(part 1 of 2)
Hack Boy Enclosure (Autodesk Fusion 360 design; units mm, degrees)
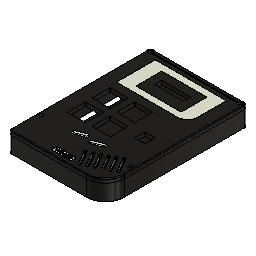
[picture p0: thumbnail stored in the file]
part number: 2026-02-14-20-05-58-561
sketch "Sketch1" plane through (0, 0, 0) normal (0, 0, 1) x axis (1, 0, 0)
  line L1 (63.94, 0) -> (0, 0)
  line L2 (63.94, 79.2) -> (63.94, 0)
  line L3 (0, 79.2) -> (63.94, 79.2)
  line L4 (0, 0) -> (0, 79.2)
  point P1 (0, 0)
  point P2 (0, 0)
  point P5 (0, 79.2)
  horizontal L1
  vertical L2
  horizontal L3
  vertical L4
  coincident P1 P2
  dimension "d1" distance P2 P5 = 79.2
  dimension "d2" distance L2 L4 = 63.94
sketch "Sketch3" plane through (0, 0, 0) normal (0, 0, 1) x axis (1, 0, 0)
  line L1 (0, 0) -> (0, 79.2)
  line L2 (63.94, 79.2) -> (63.94, 0)
  line L3 (0, 79.2) -> (63.94, 79.2)
  line L4 (63.94, 0) -> (0, 0)
  line L5 (69.47, 84.73) -> (-5.53, 84.73)
  line L6 (69.47, -25.27) -> (69.47, 84.73)
  line L7 (-5.53, -25.27) -> (69.47, -25.27)
  line L8 (-5.53, 84.73) -> (-5.53, -25.27)
  circle C1 centre (66.47, -3) radius 1.45
  circle C2 centre (-2.53, -3) radius 1.45
  circle C3 centre (-2.53, 81.73) radius 1.45
  circle C4 centre (66.47, 81.73) radius 1.45
  point P7 (-2.53, -3)
  point P6 (66.47, -3)
  point P9 (66.47, 81.73)
  point P8 (-2.53, 81.73)
  horizontal L5
  vertical L6
  horizontal L7
  vertical L8
  dimension "d11" diameter C1 = 2.9
  dimension "d14" diameter C2 = 2.9
  dimension "d20" diameter C3 = 2.9
  dimension "d23" diameter C4 = 2.9
  dimension "d30" distance L1 L8 = 5.53
  dimension "d31" distance L2 L6 = 5.53
  dimension "d32" distance L3 L5 = 5.53
  dimension "d33" distance L4 L7 = 25.27
  dimension "d35" distance P7 L8 = 3
  dimension "d36" distance L4 P7 = 3
  dimension "d37" distance L4 P6 = 3
  dimension "d38" distance P6 L6 = 3
  dimension "d39" distance P9 L6 = 3
  dimension "d40" distance P9 L5 = 3
  dimension "d41" distance P8 L5 = 3
  dimension "d42" distance P8 L8 = 3
extrude "Extrude1" new body sketch "Sketch3" along normal blind 3
extrude "Extrude2" add of existing geometry blind 10
extrude "Extrude3" add sketch "Sketch1" along normal blind 3
fillet "Fillet1" radius 15
fillet "Fillet2" radius 2
fillet "Fillet3" radius 2
fillet "Fillet4" radius 2
sketch "Sketch4" plane through (0, 0, 0) normal (0, 0, 1) x axis (1, 0, 0)
extrude "Extrude4" new body of existing geometry blind 3
move "Move1"
surface_patch "SurfacePatch5"
extrude "Extrude9" add of existing geometry blind -7
move "Move3"
sketch "Sketch10" plane through (0, 0, 3) normal (0, 0, 1) x axis (1, 0, 0)
move "Move4"
sketch "plate-2026-02-15T00_46_07.612Z" plane through (0, 0, 16) normal (0, 0, 1) x axis (1, 0, 0)
  line L1 (19.1671, 42.1434) -> (6.1671, 42.1434)
  line L2 (19.1671, 28.1434) -> (6.1671, 28.1434)
  line L3 (5.6671, 28.6434) -> (5.6671, 41.6434)
  line L4 (19.6671, 28.6434) -> (19.6671, 41.6434)
  line L5 (38.2171, 42.1434) -> (25.2171, 42.1434)
  line L6 (38.2171, 28.1434) -> (25.2171, 28.1434)
  line L7 (24.7171, 28.6434) -> (24.7171, 41.6434)
  line L8 (38.7171, 28.6434) -> (38.7171, 41.6434)
  line L9 (19.1671, 23.0934) -> (6.1671, 23.0934)
  line L10 (19.1671, 9.0934) -> (6.1671, 9.0934)
  line L11 (5.6671, 9.5934) -> (5.6671, 22.5934)
  line L12 (19.6671, 9.5934) -> (19.6671, 22.5934)
  line L13 (38.2171, 23.0934) -> (25.2171, 23.0934)
  line L14 (38.2171, 9.0934) -> (25.2171, 9.0934)
  line L15 (24.7171, 9.5934) -> (24.7171, 22.5934)
  line L16 (38.7171, 9.5934) -> (38.7171, 22.5934)
  line L17 (41.2421, 6.5684) -> (3.1421, 6.5684)
  line L18 (41.2421, 44.6684) -> (3.1421, 44.6684)
  line L19 (3.1421, 44.6684) -> (3.1421, 6.5684)
  line L20 (41.2421, 44.6684) -> (41.2421, 6.5684)
  arc A1 centre (6.1671, 41.6434) radius 0.5 clockwise from (5.6671, 41.6434) to (6.1671, 42.1434)
  arc A2 centre (19.1671, 41.6434) radius 0.5 clockwise from (19.1671, 42.1434) to (19.6671, 41.6434)
  arc A3 centre (6.1671, 28.6434) radius 0.5 clockwise from (6.1671, 28.1434) to (5.6671, 28.6434)
  arc A4 centre (19.1671, 28.6434) radius 0.5 clockwise from (19.6671, 28.6434) to (19.1671, 28.1434)
  arc A5 centre (25.2171, 41.6434) radius 0.5 clockwise from (24.7171, 41.6434) to (25.2171, 42.1434)
  arc A6 centre (38.2171, 41.6434) radius 0.5 clockwise from (38.2171, 42.1434) to (38.7171, 41.6434)
  arc A7 centre (25.2171, 28.6434) radius 0.5 clockwise from (25.2171, 28.1434) to (24.7171, 28.6434)
  arc A8 centre (38.2171, 28.6434) radius 0.5 clockwise from (38.7171, 28.6434) to (38.2171, 28.1434)
  arc A9 centre (6.1671, 22.5934) radius 0.5 clockwise from (5.6671, 22.5934) to (6.1671, 23.0934)
  arc A10 centre (19.1671, 22.5934) radius 0.5 clockwise from (19.1671, 23.0934) to (19.6671, 22.5934)
  arc A11 centre (6.1671, 9.5934) radius 0.5 clockwise from (6.1671, 9.0934) to (5.6671, 9.5934)
  arc A12 centre (19.1671, 9.5934) radius 0.5 clockwise from (19.6671, 9.5934) to (19.1671, 9.0934)
  arc A13 centre (25.2171, 22.5934) radius 0.5 clockwise from (24.7171, 22.5934) to (25.2171, 23.0934)
  arc A14 centre (38.2171, 22.5934) radius 0.5 clockwise from (38.2171, 23.0934) to (38.7171, 22.5934)
  arc A15 centre (25.2171, 9.5934) radius 0.5 clockwise from (25.2171, 9.0934) to (24.7171, 9.5934)
  arc A16 centre (38.2171, 9.5934) radius 0.5 clockwise from (38.7171, 9.5934) to (38.2171, 9.0934)
extrude "Extrude10" cut sketch "plate-2026-02-15T00_46_07.612Z" profile of L1 L2 L3 L4 A1 A2 A3 A4 L5 L6 L7 L8 A5 A6 A7 A8 L9 L10 L11 L12 A9 A10 A11 A12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 against normal blind 4
sketch "plate-2026-03-27T04_05_42.671Z" plane through (0, 0, 16) normal (0, 0, 1) x axis (1, 0, 0)
  line L1 (59.3897, 28.9519) -> (46.3897, 28.9519)
  line L2 (59.3897, 14.9519) -> (46.3897, 14.9519)
  line L3 (45.8897, 15.4519) -> (45.8897, 28.4519)
  line L4 (59.8897, 15.4519) -> (59.8897, 28.4519)
  line L5 (62.4147, 12.4269) -> (43.3647, 12.4269)
  line L6 (62.4147, 31.4769) -> (43.3647, 31.4769)
  line L7 (43.3647, 31.4769) -> (43.3647, 12.4269)
  line L8 (62.4147, 31.4769) -> (62.4147, 12.4269)
  arc A1 centre (46.3897, 28.4519) radius 0.5 clockwise from (45.8897, 28.4519) to (46.3897, 28.9519)
  arc A2 centre (59.3897, 28.4519) radius 0.5 clockwise from (59.3897, 28.9519) to (59.8897, 28.4519)
  arc A3 centre (46.3897, 15.4519) radius 0.5 clockwise from (46.3897, 14.9519) to (45.8897, 15.4519)
  arc A4 centre (59.3897, 15.4519) radius 0.5 clockwise from (59.8897, 15.4519) to (59.3897, 14.9519)
extrude "Extrude11" cut sketch "plate-2026-03-27T04_05_42.671Z" profile of L1 L2 L3 L4 A1 A2 A3 A4 against normal blind 4
sketch "Sketch13" plane through (0, 0, 16) normal (0, 0, 1) x axis (-1, 0, 0)
  line L1 (-45.8897, -28.4519) -> (-45.8897, -15.4519)
  line L2 (-59.3897, -28.9519) -> (-46.3897, -28.9519)
  line L3 (-59.8897, -15.4519) -> (-59.8897, -28.4519)
  line L4 (-46.3897, -14.9519) -> (-59.3897, -14.9519)
  line L5 (-5.6671, -41.6434) -> (-5.6671, -28.6434)
  line L6 (-19.1671, -42.1434) -> (-6.1671, -42.1434)
  line L7 (-19.6671, -28.6434) -> (-19.6671, -41.6434)
  line L8 (-6.1671, -28.1434) -> (-19.1671, -28.1434)
  line L9 (-5.6671, -22.5934) -> (-5.6671, -9.5934)
  line L10 (-19.1671, -23.0934) -> (-6.1671, -23.0934)
  line L11 (-19.6671, -9.5934) -> (-19.6671, -22.5934)
  line L12 (-6.1671, -9.0934) -> (-19.1671, -9.0934)
  line L13 (-24.7171, -41.6434) -> (-24.7171, -28.6434)
  line L14 (-38.2171, -42.1434) -> (-25.2171, -42.1434)
  line L15 (-38.7171, -28.6434) -> (-38.7171, -41.6434)
  line L16 (-25.2171, -28.1434) -> (-38.2171, -28.1434)
  line L17 (-24.7171, -22.5934) -> (-24.7171, -9.5934)
  line L18 (-38.2171, -23.0934) -> (-25.2171, -23.0934)
  line L19 (-38.7171, -9.5934) -> (-38.7171, -22.5934)
  line L20 (-25.2171, -9.0934) -> (-38.2171, -9.0934)
  line L21 (3.53, -84.73) -> (-67.47, -84.73)
  line L22 (5.53, 23.27) -> (5.53, -82.73)
  line L23 (-54.47, 25.27) -> (3.53, 25.27)
  line L24 (-69.47, -82.73) -> (-69.47, 10.27)
  line L25 (-43.16, -67.23) -> (-20.78, -67.23)
  line L26 (-43.16, -61.65) -> (-43.16, -67.23)
  line L27 (-20.78, -61.65) -> (-43.16, -61.65)
  line L28 (-20.78, -67.23) -> (-20.78, -61.65)
  arc A1 centre (-46.3897, -28.4519) radius 0.5 clockwise from (-45.8897, -28.4519) to (-46.3897, -28.9519)
  arc A2 centre (-59.3897, -28.4519) radius 0.5 clockwise from (-59.3897, -28.9519) to (-59.8897, -28.4519)
  arc A3 centre (-59.3897, -15.4519) radius 0.5 clockwise from (-59.8897, -15.4519) to (-59.3897, -14.9519)
  arc A4 centre (-46.3897, -15.4519) radius 0.5 clockwise from (-46.3897, -14.9519) to (-45.8897, -15.4519)
  arc A5 centre (-6.1671, -41.6434) radius 0.5 clockwise from (-5.6671, -41.6434) to (-6.1671, -42.1434)
  arc A6 centre (-19.1671, -41.6434) radius 0.5 clockwise from (-19.1671, -42.1434) to (-19.6671, -41.6434)
  arc A7 centre (-19.1671, -28.6434) radius 0.5 clockwise from (-19.6671, -28.6434) to (-19.1671, -28.1434)
  arc A8 centre (-6.1671, -28.6434) radius 0.5 clockwise from (-6.1671, -28.1434) to (-5.6671, -28.6434)
  arc A9 centre (-6.1671, -22.5934) radius 0.5 clockwise from (-5.6671, -22.5934) to (-6.1671, -23.0934)
  arc A10 centre (-19.1671, -22.5934) radius 0.5 clockwise from (-19.1671, -23.0934) to (-19.6671, -22.5934)
  arc A11 centre (-19.1671, -9.5934) radius 0.5 clockwise from (-19.6671, -9.5934) to (-19.1671, -9.0934)
  arc A12 centre (-6.1671, -9.5934) radius 0.5 clockwise from (-6.1671, -9.0934) to (-5.6671, -9.5934)
  arc A13 centre (-25.2171, -41.6434) radius 0.5 clockwise from (-24.7171, -41.6434) to (-25.2171, -42.1434)
  arc A14 centre (-38.2171, -41.6434) radius 0.5 clockwise from (-38.2171, -42.1434) to (-38.7171, -41.6434)
  arc A15 centre (-38.2171, -28.6434) radius 0.5 clockwise from (-38.7171, -28.6434) to (-38.2171, -28.1434)
  arc A16 centre (-25.2171, -28.6434) radius 0.5 clockwise from (-25.2171, -28.1434) to (-24.7171, -28.6434)
  arc A17 centre (-25.2171, -22.5934) radius 0.5 clockwise from (-24.7171, -22.5934) to (-25.2171, -23.0934)
  arc A18 centre (-38.2171, -22.5934) radius 0.5 clockwise from (-38.2171, -23.0934) to (-38.7171, -22.5934)
  arc A19 centre (-38.2171, -9.5934) radius 0.5 clockwise from (-38.7171, -9.5934) to (-38.2171, -9.0934)
  arc A20 centre (-25.2171, -9.5934) radius 0.5 clockwise from (-25.2171, -9.0934) to (-24.7171, -9.5934)
  arc A21 centre (-67.47, -82.73) radius 2 clockwise from (-67.47, -84.73) to (-69.47, -82.73)
  arc A22 centre (3.53, -82.73) radius 2 clockwise from (5.53, -82.73) to (3.53, -84.73)
  arc A23 centre (3.53, 23.27) radius 2 clockwise from (3.53, 25.27) to (5.53, 23.27)
  arc A24 centre (-54.47, 10.27) radius 15 clockwise from (-69.47, 10.27) to (-54.47, 25.27)
  circle C1 centre (-66.47, -81.73) radius 1.45
  circle C2 centre (-66.47, 3) radius 1.45
  circle C3 centre (2.53, 3) radius 1.45
  circle C4 centre (2.53, -81.73) radius 1.45
  point P78 (-20.78, -67.23)
  point P81 (-20.78, -61.65)
  point P79 (-43.16, -67.23)
  horizontal L25
  vertical L26
  horizontal L27
  vertical L28
  dimension "d73" distance P78 P81 = 5.58
  dimension "d74" distance P78 P79 = 22.38
  dimension "d75" distance L22 L28 = 26.31
  dimension "d76" distance L21 L25 = 17.5
extrude "Extrude12" cut sketch "Sketch13" profile of L25 L26 L27 L28 against normal blind 4
sketch "Sketch14" plane through (0, 0, 16) normal (0, 0, 1) x axis (-1, 0, 0)
  line L1 (-43.16, -61.65) -> (-43.16, -67.23)
  line L2 (-20.78, -61.65) -> (-43.16, -61.65)
  line L3 (-20.78, -67.23) -> (-20.78, -61.65)
  line L4 (-43.16, -67.23) -> (-20.78, -67.23)
  line L5 (-45.8897, -28.4519) -> (-45.8897, -15.4519)
  line L6 (-59.3897, -28.9519) -> (-46.3897, -28.9519)
  line L7 (-59.8897, -15.4519) -> (-59.8897, -28.4519)
  line L8 (-46.3897, -14.9519) -> (-59.3897, -14.9519)
  line L9 (-5.6671, -41.6434) -> (-5.6671, -28.6434)
  line L10 (-19.1671, -42.1434) -> (-6.1671, -42.1434)
  line L11 (-19.6671, -28.6434) -> (-19.6671, -41.6434)
  line L12 (-6.1671, -28.1434) -> (-19.1671, -28.1434)
  line L13 (-5.6671, -22.5934) -> (-5.6671, -9.5934)
  line L14 (-19.1671, -23.0934) -> (-6.1671, -23.0934)
  line L15 (-19.6671, -9.5934) -> (-19.6671, -22.5934)
  line L16 (-6.1671, -9.0934) -> (-19.1671, -9.0934)
  line L17 (-24.7171, -41.6434) -> (-24.7171, -28.6434)
  line L18 (-38.2171, -42.1434) -> (-25.2171, -42.1434)
  line L19 (-38.7171, -28.6434) -> (-38.7171, -41.6434)
  line L20 (-25.2171, -28.1434) -> (-38.2171, -28.1434)
  line L21 (-24.7171, -22.5934) -> (-24.7171, -9.5934)
  line L22 (-38.2171, -23.0934) -> (-25.2171, -23.0934)
  line L23 (-38.7171, -9.5934) -> (-38.7171, -22.5934)
  line L24 (-25.2171, -9.0934) -> (-38.2171, -9.0934)
  line L25 (3.53, -84.73) -> (-67.47, -84.73)
  line L26 (5.53, 23.27) -> (5.53, -82.73)
  line L27 (-54.47, 25.27) -> (3.53, 25.27)
  line L28 (-69.47, -82.73) -> (-69.47, 10.27)
  line L29 (-58.47, -78.4365) -> (-5.47, -78.4365)
  line L30 (-59.47, -56.4365) -> (-59.47, -77.4365)
  line L31 (-5.47, -48.4365) -> (-51.47, -48.4365)
  line L32 (-4.47, -77.4365) -> (-4.47, -49.4365)
  arc A1 centre (-46.3897, -28.4519) radius 0.5 clockwise from (-45.8897, -28.4519) to (-46.3897, -28.9519)
  arc A2 centre (-59.3897, -28.4519) radius 0.5 clockwise from (-59.3897, -28.9519) to (-59.8897, -28.4519)
  arc A3 centre (-59.3897, -15.4519) radius 0.5 clockwise from (-59.8897, -15.4519) to (-59.3897, -14.9519)
  arc A4 centre (-46.3897, -15.4519) radius 0.5 clockwise from (-46.3897, -14.9519) to (-45.8897, -15.4519)
  arc A5 centre (-6.1671, -41.6434) radius 0.5 clockwise from (-5.6671, -41.6434) to (-6.1671, -42.1434)
  arc A6 centre (-19.1671, -41.6434) radius 0.5 clockwise from (-19.1671, -42.1434) to (-19.6671, -41.6434)
  arc A7 centre (-19.1671, -28.6434) radius 0.5 clockwise from (-19.6671, -28.6434) to (-19.1671, -28.1434)
  arc A8 centre (-6.1671, -28.6434) radius 0.5 clockwise from (-6.1671, -28.1434) to (-5.6671, -28.6434)
  arc A9 centre (-6.1671, -22.5934) radius 0.5 clockwise from (-5.6671, -22.5934) to (-6.1671, -23.0934)
  arc A10 centre (-19.1671, -22.5934) radius 0.5 clockwise from (-19.1671, -23.0934) to (-19.6671, -22.5934)
  arc A11 centre (-19.1671, -9.5934) radius 0.5 clockwise from (-19.6671, -9.5934) to (-19.1671, -9.0934)
  arc A12 centre (-6.1671, -9.5934) radius 0.5 clockwise from (-6.1671, -9.0934) to (-5.6671, -9.5934)
  arc A13 centre (-25.2171, -41.6434) radius 0.5 clockwise from (-24.7171, -41.6434) to (-25.2171, -42.1434)
  arc A14 centre (-38.2171, -41.6434) radius 0.5 clockwise from (-38.2171, -42.1434) to (-38.7171, -41.6434)
  arc A15 centre (-38.2171, -28.6434) radius 0.5 clockwise from (-38.7171, -28.6434) to (-38.2171, -28.1434)
  arc A16 centre (-25.2171, -28.6434) radius 0.5 clockwise from (-25.2171, -28.1434) to (-24.7171, -28.6434)
  arc A17 centre (-25.2171, -22.5934) radius 0.5 clockwise from (-24.7171, -22.5934) to (-25.2171, -23.0934)
  arc A18 centre (-38.2171, -22.5934) radius 0.5 clockwise from (-38.2171, -23.0934) to (-38.7171, -22.5934)
  arc A19 centre (-38.2171, -9.5934) radius 0.5 clockwise from (-38.7171, -9.5934) to (-38.2171, -9.0934)
  arc A20 centre (-25.2171, -9.5934) radius 0.5 clockwise from (-25.2171, -9.0934) to (-24.7171, -9.5934)
  arc A21 centre (-67.47, -82.73) radius 2 clockwise from (-67.47, -84.73) to (-69.47, -82.73)
  arc A22 centre (3.53, -82.73) radius 2 clockwise from (5.53, -82.73) to (3.53, -84.73)
  arc A23 centre (3.53, 23.27) radius 2 clockwise from (3.53, 25.27) to (5.53, 23.27)
  arc A24 centre (-54.47, 10.27) radius 15 clockwise from (-69.47, 10.27) to (-54.47, 25.27)
  circle C1 centre (-66.47, -81.73) radius 1.45
  circle C2 centre (-66.47, 3) radius 1.45
  circle C3 centre (2.53, 3) radius 1.45
  circle C4 centre (2.53, -81.73) radius 1.45
  arc A25 centre (-51.47, -56.4365) radius 8 clockwise from (-59.47, -56.4365) to (-51.47, -48.4365)
  arc A26 centre (-58.47, -77.4365) radius 1 clockwise from (-58.47, -78.4365) to (-59.47, -77.4365)
  arc A27 centre (-5.47, -77.4365) radius 1 clockwise from (-4.47, -77.4365) to (-5.47, -78.4365)
  arc A28 centre (-5.47, -49.4365) radius 1 clockwise from (-5.47, -48.4365) to (-4.47, -49.4365)
  horizontal L29
  vertical L30
  horizontal L31
  vertical L32
  tangent L30 A25
  tangent L31 A25
  tangent L29 A26
  tangent L30 A26
  tangent L29 A27
  tangent L32 A27
  equal A26 A27
  tangent L31 A28
  tangent L32 A28
  dimension "d81" distance L26 L32 = 10
  dimension "d82" distance L25 L29 = 6.2935
  dimension "d83" radius A25 = 8
  dimension "d84" radius A26 = 1
  dimension "d85" radius A28 = 1
sketch "Sketch15" plane through (0, 0, 16) normal (0, 0, 1) x axis (-1, 0, 0)
  line L1 (-49.47, -73.4365) -> (-14.47, -73.4365)
  line L2 (-49.47, -53.4365) -> (-49.47, -73.4365)
  line L3 (-14.47, -53.4365) -> (-49.47, -53.4365)
  line L4 (-14.47, -73.4365) -> (-14.47, -53.4365)
  line L5 (-59.47, -56.4365) -> (-59.47, -77.4365)
  line L6 (-58.47, -78.4365) -> (-5.47, -78.4365)
  point P2 (-14.47, -73.4365)
  point P3 (-49.47, -73.4365)
  point P5 (-14.47, -53.4365)
  horizontal L1
  vertical L2
  horizontal L3
  vertical L4
  dimension "d86" distance P2 P3 = 35
  dimension "d87" distance P2 P5 = 20
  dimension "d88" distance L2 L5 = 10
  dimension "d89" distance L1 L6 = 5
extrude "Extrude13" cut sketch "Sketch14" profile of L1 L2 L3 L4 L29 L30 L31 L32 A25 A26 A27 A28 against normal blind 0.1
extrude "Extrude14" cut sketch "Sketch15" profile of L1 L2 L3 L4 against normal blind 0.2
sketch "Sketch16" plane through (0, 0, 16) normal (0, 0, 1) x axis (-1, 0, 0)
  line L1 (-4.47, -77.4365) -> (-4.47, -49.4365)
  line L2 (-58.47, -78.4365) -> (-5.47, -78.4365)
  line L3 (-59.47, -56.4365) -> (-59.47, -77.4365)
  line L4 (-5.47, -48.4365) -> (-51.47, -48.4365)
  line L5 (-45.8897, -28.4519) -> (-45.8897, -15.4519)
  line L6 (-59.3897, -28.9519) -> (-46.3897, -28.9519)
  line L7 (-59.8897, -15.4519) -> (-59.8897, -28.4519)
  line L8 (-46.3897, -14.9519) -> (-59.3897, -14.9519)
  line L9 (-5.6671, -41.6434) -> (-5.6671, -28.6434)
  line L10 (-19.1671, -42.1434) -> (-6.1671, -42.1434)
  line L11 (-19.6671, -28.6434) -> (-19.6671, -41.6434)
  line L12 (-6.1671, -28.1434) -> (-19.1671, -28.1434)
  line L13 (-5.6671, -22.5934) -> (-5.6671, -9.5934)
  line L14 (-19.1671, -23.0934) -> (-6.1671, -23.0934)
  line L15 (-19.6671, -9.5934) -> (-19.6671, -22.5934)
  line L16 (-6.1671, -9.0934) -> (-19.1671, -9.0934)
  line L17 (-24.7171, -41.6434) -> (-24.7171, -28.6434)
  line L18 (-38.2171, -42.1434) -> (-25.2171, -42.1434)
  line L19 (-38.7171, -28.6434) -> (-38.7171, -41.6434)
  line L20 (-25.2171, -28.1434) -> (-38.2171, -28.1434)
  line L21 (-24.7171, -22.5934) -> (-24.7171, -9.5934)
  line L22 (-38.2171, -23.0934) -> (-25.2171, -23.0934)
  line L23 (-38.7171, -9.5934) -> (-38.7171, -22.5934)
  line L24 (-25.2171, -9.0934) -> (-38.2171, -9.0934)
  line L25 (3.53, -84.73) -> (-67.47, -84.73)
  line L26 (5.53, 23.27) -> (5.53, -82.73)
  line L27 (-54.47, 25.27) -> (3.53, 25.27)
  line L28 (-69.47, -82.73) -> (-69.47, 10.27)
  line L29 (-65.0763, -82.13) -> (1.1363, -82.13)
  line L30 (-65.0763, -81.33) -> (1.1363, -81.33)
  line L31 (5.53, -82.13) -> (3.9237, -82.13)
  line L32 (5.53, -81.33) -> (3.9237, -81.33)
  line L33 (-69.47, -82.13) -> (-67.8637, -82.13)
  line L34 (-69.47, -81.33) -> (-67.8637, -81.33)
  line L35 (2.13, -84.73) -> (2.13, -83.1237)
  line L36 (2.93, -84.73) -> (2.93, -83.1237)
  line L37 (-66.87, -84.73) -> (-66.87, -83.1237)
  line L38 (-66.07, -84.73) -> (-66.07, -83.1237)
  line L39 (4.18, -81.33) -> (4.18, -82.13)
  line L40 (2.13, -83.38) -> (2.93, -83.38)
  line L41 (0.88, -81.33) -> (0.88, -82.13)
  line L42 (-64.82, -81.33) -> (-64.82, -82.13)
  line L43 (-66.87, -83.38) -> (-66.07, -83.38)
  line L44 (-68.12, -81.33) -> (-68.12, -82.13)
  arc A1 centre (-5.47, -77.4365) radius 1 clockwise from (-4.47, -77.4365) to (-5.47, -78.4365)
  arc A2 centre (-58.47, -77.4365) radius 1 clockwise from (-58.47, -78.4365) to (-59.47, -77.4365)
  arc A3 centre (-51.47, -56.4365) radius 8 clockwise from (-59.47, -56.4365) to (-51.47, -48.4365)
  arc A4 centre (-5.47, -49.4365) radius 1 clockwise from (-5.47, -48.4365) to (-4.47, -49.4365)
  arc A5 centre (-46.3897, -28.4519) radius 0.5 clockwise from (-45.8897, -28.4519) to (-46.3897, -28.9519)
  arc A6 centre (-59.3897, -28.4519) radius 0.5 clockwise from (-59.3897, -28.9519) to (-59.8897, -28.4519)
  arc A7 centre (-59.3897, -15.4519) radius 0.5 clockwise from (-59.8897, -15.4519) to (-59.3897, -14.9519)
  arc A8 centre (-46.3897, -15.4519) radius 0.5 clockwise from (-46.3897, -14.9519) to (-45.8897, -15.4519)
  arc A9 centre (-6.1671, -41.6434) radius 0.5 clockwise from (-5.6671, -41.6434) to (-6.1671, -42.1434)
  arc A10 centre (-19.1671, -41.6434) radius 0.5 clockwise from (-19.1671, -42.1434) to (-19.6671, -41.6434)
  arc A11 centre (-19.1671, -28.6434) radius 0.5 clockwise from (-19.6671, -28.6434) to (-19.1671, -28.1434)
  arc A12 centre (-6.1671, -28.6434) radius 0.5 clockwise from (-6.1671, -28.1434) to (-5.6671, -28.6434)
  arc A13 centre (-6.1671, -22.5934) radius 0.5 clockwise from (-5.6671, -22.5934) to (-6.1671, -23.0934)
  arc A14 centre (-19.1671, -22.5934) radius 0.5 clockwise from (-19.1671, -23.0934) to (-19.6671, -22.5934)
  arc A15 centre (-19.1671, -9.5934) radius 0.5 clockwise from (-19.6671, -9.5934) to (-19.1671, -9.0934)
  arc A16 centre (-6.1671, -9.5934) radius 0.5 clockwise from (-6.1671, -9.0934) to (-5.6671, -9.5934)
  arc A17 centre (-25.2171, -41.6434) radius 0.5 clockwise from (-24.7171, -41.6434) to (-25.2171, -42.1434)
  arc A18 centre (-38.2171, -41.6434) radius 0.5 clockwise from (-38.2171, -42.1434) to (-38.7171, -41.6434)
  arc A19 centre (-38.2171, -28.6434) radius 0.5 clockwise from (-38.7171, -28.6434) to (-38.2171, -28.1434)
  arc A20 centre (-25.2171, -28.6434) radius 0.5 clockwise from (-25.2171, -28.1434) to (-24.7171, -28.6434)
  arc A21 centre (-25.2171, -22.5934) radius 0.5 clockwise from (-24.7171, -22.5934) to (-25.2171, -23.0934)
  arc A22 centre (-38.2171, -22.5934) radius 0.5 clockwise from (-38.2171, -23.0934) to (-38.7171, -22.5934)
  arc A23 centre (-38.2171, -9.5934) radius 0.5 clockwise from (-38.7171, -9.5934) to (-38.2171, -9.0934)
  arc A24 centre (-25.2171, -9.5934) radius 0.5 clockwise from (-25.2171, -9.0934) to (-24.7171, -9.5934)
  arc A25 centre (-67.47, -82.73) radius 2 clockwise from (-67.47, -84.73) to (-69.47, -82.73)
  arc A26 centre (3.53, -82.73) radius 2 clockwise from (5.53, -82.73) to (3.53, -84.73)
  arc A27 centre (3.53, 23.27) radius 2 clockwise from (3.53, 25.27) to (5.53, 23.27)
  arc A28 centre (-54.47, 10.27) radius 15 clockwise from (-69.47, 10.27) to (-54.47, 25.27)
  circle C1 centre (-66.47, -81.73) radius 1.45
  circle C2 centre (-66.47, 3) radius 1.45
  circle C3 centre (2.53, 3) radius 1.45
  circle C4 centre (2.53, -81.73) radius 1.45
  point P90 (1.1363, -82.13)
  point P91 (-65.0763, -82.13)
  point P92 (1.1363, -81.33)
  point P93 (-65.0763, -81.33)
  point P94 (3.9237, -82.13)
  point P95 (5.53, -82.13)
  point P96 (3.9237, -81.33)
  point P97 (5.53, -81.33)
  point P98 (-67.8637, -82.13)
  point P99 (-69.47, -82.13)
  point P100 (-67.8637, -81.33)
  point P101 (-69.47, -81.33)
  point P102 (2.13, -83.1237)
  point P103 (2.13, -84.73)
  point P104 (2.93, -83.1237)
  point P105 (2.93, -84.73)
  point P106 (-66.87, -83.1237)
  point P107 (-66.87, -84.73)
  point P108 (-66.07, -83.1237)
  point P109 (-66.07, -84.73)
  point P110 (4.18, -82.13)
  point P111 (4.18, -81.33)
  point P112 (2.93, -83.38)
  point P113 (2.13, -83.38)
  point P114 (0.88, -82.13)
  point P115 (0.88, -81.33)
  point P116 (-64.82, -82.13)
  point P117 (-64.82, -81.33)
  point P118 (-66.07, -83.38)
  point P119 (-66.87, -83.38)
  point P120 (-68.12, -82.13)
  point P121 (-68.12, -81.33)
  point P89 (2.53, -81.73)
  point P86 (-66.47, -81.73)
  coincident C4 P90
  coincident C1 P91
  parallel L25 L29
  coincident C4 P92
  coincident C1 P93
  parallel L25 L30
  coincident C4 P94
  coincident L26 P95
  perpendicular L26 L31
  coincident C4 P96
  coincident L26 P97
  perpendicular L26 L32
  coincident C1 P98
  coincident L28 P99
  perpendicular L28 L33
  coincident C1 P100
  coincident L28 P101
  perpendicular L28 L34
  coincident C4 P102
  coincident L25 P103
  perpendicular L25 L35
  coincident C4 P104
  coincident L25 P105
  perpendicular L25 L36
  coincident C1 P106
  coincident L25 P107
  perpendicular L25 L37
  coincident C1 P108
  coincident L25 P109
  perpendicular L25 L38
  coincident L31 P110
  coincident L32 P111
  perpendicular L32 L39
  coincident L36 P112
  coincident L35 P113
  perpendicular L35 L40
  coincident L29 P114
  coincident L30 P115
  perpendicular L30 L41
  coincident L29 P116
  coincident L30 P117
  perpendicular L30 L42
  coincident L38 P118
  coincident L37 P119
  perpendicular L37 L43
  coincident L33 P120
  coincident L34 P121
  perpendicular L34 L44
  dimension "d116" distance P89 L39 = 1.65
  dimension "d117" distance P89 L40 = 1.65
  dimension "d118" distance P89 L41 = 1.65
  dimension "d119" distance P86 L42 = 1.65
  dimension "d120" distance P86 L43 = 1.65
  dimension "d121" distance P86 L44 = 1.65
sketch "Sketch19" plane through (69.47, 0, 0) normal (1, 0, 0) x axis (0, 1, 0)
  line L1 (-10.27, 16) -> (82.73, 16)
  line L2 (-10.27, 13) -> (-10.27, 16)
  line L3 (82.73, 13) -> (-10.27, 13)
  line L4 (82.73, 16) -> (82.73, 13)
  line L5 (82.13, 8.5) -> (82.13, 16)
  line L6 (81.33, 8.5) -> (81.33, 16)
  line L7 (82.73, 8.5) -> (82.13, 8.5)
  line L8 (-10, 8.5) -> (81.33, 8.5)
  line L9 (82.73, 7.7) -> (82.73, 8.5)
  line L10 (-10.3, 7.7) -> (82.73, 7.7)
  line L11 (-10.3, 8.5) -> (-10, 8.5)
  line L12 (-10.3, 8.5) -> (-10.3, 7.7)
  point P6 (82.13, 16)
  point P8 (81.33, 16)
  point P7 (82.13, 8.5)
  point P10 (82.73, 8.5)
  point P12 (82.73, 7.7)
  coincident L1 P6
  perpendicular L1 L5
  coincident L1 P8
  perpendicular L1 L6
  perpendicular L5 L7
  perpendicular L6 L8
  perpendicular L7 L9
  perpendicular L9 L10
  parallel L8 L11
  perpendicular L11 L12
  dimension "d114" distance L5 L6 = 0.8
  dimension "d115" distance L4 L5 = 0.6
  dimension "d122" distance P7 P10 = 0.6
  dimension "d123" distance P10 P12 = 0.8
sketch "Sketch20" plane through (0, 79.2, 0) normal (0, -1, 0) x axis (1, 0, 0)
  line L1 (63.94, 3) -> (0, 3)
  line L2 (63.94, 13) -> (63.94, 3)
  line L3 (0, 13) -> (63.94, 13)
  line L4 (0, 3) -> (0, 13)
extrude "Extrude20" cut sketch "Sketch16" profile of L25 L26 L28 L29 L30 L31 L32 L33 L34 L35 L36 L37 L38 L39 L40 L41 L42 L43 L44 against normal blind 0.2
sketch "Sketch22" plane through (0, 0, 16) normal (0, 0, 1) x axis (-1, 0, 0)
  line L1 (-28.7155, -2.375) -> (-21.198, 0.3612)
  line L2 (-30.3393, -0.8376) -> (-29.9973, -1.7773)
  line L3 (-22.2241, 3.1803) -> (-29.7416, 0.4441)
  line L4 (-20.6003, 1.6429) -> (-20.9423, 2.5826)
  line L5 (-33.6003, 1.6429) -> (-33.9423, 2.5826)
  line L6 (-35.2241, 3.1803) -> (-42.742, 0.444)
  line L7 (-41.7162, -2.3752) -> (-34.198, 0.3612)
  line L8 (-43.3398, -0.8375) -> (-42.998, -1.7773)
  line L9 (5.53, 23.27) -> (5.53, -81.33)
  line L10 (-69.47, 10) -> (-69.47, -81.33)
  arc A1 centre (-29.0576, -1.4353) radius 1 clockwise from (-28.7155, -2.375) to (-29.9973, -1.7773)
  arc A2 centre (-29.3996, -0.4956) radius 1 clockwise from (-30.3393, -0.8376) to (-29.7416, 0.4441)
  arc A3 centre (-21.882, 2.2406) radius 1 clockwise from (-22.2241, 3.1803) to (-20.9423, 2.5826)
  arc A4 centre (-21.54, 1.3009) radius 1 clockwise from (-20.6003, 1.6429) to (-21.198, 0.3612)
  arc A5 centre (-42.4, -0.4957) radius 1 clockwise from (-43.3398, -0.8375) to (-42.742, 0.444)
  arc A6 centre (-34.882, 2.2406) radius 1 clockwise from (-35.2241, 3.1803) to (-33.9423, 2.5826)
  arc A7 centre (-42.0582, -1.4355) radius 1 clockwise from (-41.7162, -2.3752) to (-42.998, -1.7773)
  arc A8 centre (-34.54, 1.3009) radius 1 clockwise from (-33.6003, 1.6429) to (-34.198, 0.3612)
  point P3 (-29.6552, -2.717)
  point P4 (-21.2844, 3.5223)
  point P2 (-20.2583, 0.7032)
  point P31 (-42.6561, -2.7173)
  point P29 (-34.2844, 3.5223)
  point P30 (-33.2583, 0.7032)
  coincident P3 L1
  coincident P3 L2
  tangent L1 A1
  tangent L2 A1
  tangent L2 A2
  tangent L3 A2
  equal A1 A2
  coincident P4 L3
  coincident P4 L4
  tangent L3 A3
  tangent L4 A3
  equal A1 A3
  coincident P2 L1
  coincident P2 L4
  tangent L1 A4
  tangent L4 A4
  equal A1 A4
  coincident P31 L7
  coincident P31 L8
  tangent A7 L7
  tangent A7 L8
  tangent A5 L8
  tangent A5 L6
  equal A5 A7
  coincident P29 L6
  coincident P29 L5
  tangent A6 L6
  tangent A6 L5
  equal A6 A7
  coincident P30 L7
  coincident P30 L5
  tangent A8 L7
  tangent L5 A8
  equal A7 A8
sketch "Sketch23" plane through (0, 0, 16) normal (0, 0, 1) x axis (-1, 0, 0)
  line L1 (-50.0584, 18.8284) -> (-43.5584, 7.5701)
  line L2 (-49.4424, 19.7614) -> (-49.8754, 19.5114)
  line L3 (-42.2594, 8.3201) -> (-48.7594, 19.5784)
  line L4 (-42.8754, 7.3871) -> (-42.4424, 7.6371)
  line L5 (-54.0584, 16.8284) -> (-47.5584, 5.5701)
  line L6 (-46.8754, 5.3871) -> (-46.4424, 5.6371)
  line L7 (-46.2594, 6.3201) -> (-52.7594, 17.5784)
  line L8 (-53.4424, 17.7614) -> (-53.8754, 17.5114)
  line L9 (-50.2594, 4.3201) -> (-56.7594, 15.5784)
  line L10 (-57.4424, 15.7614) -> (-57.8754, 15.5114)
  line L11 (-58.0584, 14.8284) -> (-51.5584, 3.5701)
  line L12 (-50.8754, 3.3871) -> (-50.4424, 3.6371)
  line L13 (-54.2594, 2.3201) -> (-60.7594, 13.5784)
  line L14 (-61.4424, 13.7614) -> (-61.8754, 13.5114)
  line L15 (-62.0584, 12.8284) -> (-55.5584, 1.5701)
  line L16 (-54.8754, 1.3871) -> (-54.4424, 1.6371)
  line L17 (-58.2594, 0.3201) -> (-64.7594, 11.5784)
  line L18 (-65.4424, 11.7614) -> (-65.8754, 11.5114)
  line L19 (-66.0584, 10.8284) -> (-59.5584, -0.4299)
  line L20 (-58.8754, -0.6129) -> (-58.4424, -0.3629)
  line L21 (-38.2594, 10.3201) -> (-44.7594, 21.5784)
  line L22 (-45.4424, 21.7614) -> (-45.8754, 21.5114)
  line L23 (-46.0584, 20.8284) -> (-39.5584, 9.5701)
  line L24 (-38.8754, 9.3871) -> (-38.4424, 9.6371)
  arc A1 centre (-43.1254, 7.8201) radius 0.5 clockwise from (-42.8754, 7.3871) to (-43.5584, 7.5701)
  arc A2 centre (-42.6924, 8.0701) radius 0.5 clockwise from (-42.2594, 8.3201) to (-42.4424, 7.6371)
  arc A3 centre (-49.1924, 19.3284) radius 0.5 clockwise from (-49.4424, 19.7614) to (-48.7594, 19.5784)
  arc A4 centre (-49.6254, 19.0784) radius 0.5 clockwise from (-50.0584, 18.8284) to (-49.8754, 19.5114)
  arc A5 centre (-46.6924, 6.0701) radius 0.5 clockwise from (-46.2594, 6.3201) to (-46.4424, 5.6371)
  arc A6 centre (-47.1254, 5.8201) radius 0.5 clockwise from (-46.8754, 5.3871) to (-47.5584, 5.5701)
  arc A7 centre (-53.6254, 17.0784) radius 0.5 clockwise from (-54.0584, 16.8284) to (-53.8754, 17.5114)
  arc A8 centre (-53.1924, 17.3284) radius 0.5 clockwise from (-53.4424, 17.7614) to (-52.7594, 17.5784)
  arc A9 centre (-57.1924, 15.3284) radius 0.5 clockwise from (-57.4424, 15.7614) to (-56.7594, 15.5784)
  arc A10 centre (-51.1254, 3.8201) radius 0.5 clockwise from (-50.8754, 3.3871) to (-51.5584, 3.5701)
  arc A11 centre (-57.6254, 15.0784) radius 0.5 clockwise from (-58.0584, 14.8284) to (-57.8754, 15.5114)
  arc A12 centre (-50.6924, 4.0701) radius 0.5 clockwise from (-50.2594, 4.3201) to (-50.4424, 3.6371)
  arc A13 centre (-61.1924, 13.3284) radius 0.5 clockwise from (-61.4424, 13.7614) to (-60.7594, 13.5784)
  arc A14 centre (-55.1254, 1.8201) radius 0.5 clockwise from (-54.8754, 1.3871) to (-55.5584, 1.5701)
  arc A15 centre (-61.6254, 13.0784) radius 0.5 clockwise from (-62.0584, 12.8284) to (-61.8754, 13.5114)
  arc A16 centre (-54.6924, 2.0701) radius 0.5 clockwise from (-54.2594, 2.3201) to (-54.4424, 1.6371)
  arc A17 centre (-65.1924, 11.3284) radius 0.5 clockwise from (-65.4424, 11.7614) to (-64.7594, 11.5784)
  arc A18 centre (-59.1254, -0.1799) radius 0.5 clockwise from (-58.8754, -0.6129) to (-59.5584, -0.4299)
  arc A19 centre (-65.6254, 11.0784) radius 0.5 clockwise from (-66.0584, 10.8284) to (-65.8754, 11.5114)
  arc A20 centre (-58.6924, 0.0701) radius 0.5 clockwise from (-58.2594, 0.3201) to (-58.4424, -0.3629)
  arc A21 centre (-45.1924, 21.3284) radius 0.5 clockwise from (-45.4424, 21.7614) to (-44.7594, 21.5784)
  arc A22 centre (-39.1254, 9.8201) radius 0.5 clockwise from (-38.8754, 9.3871) to (-39.5584, 9.5701)
  arc A23 centre (-45.6254, 21.0784) radius 0.5 clockwise from (-46.0584, 20.8284) to (-45.8754, 21.5114)
  arc A24 centre (-38.6924, 10.0701) radius 0.5 clockwise from (-38.2594, 10.3201) to (-38.4424, 9.6371)
  point P2 (-43.3084, 7.1371)
  point P3 (-42.0094, 7.8871)
  point P25 (-47.3084, 5.1371)
  point P18 (-46.0094, 5.8871)
  point P40 (-51.3084, 3.1371)
  point P32 (-50.0094, 3.8871)
  point P54 (-55.3084, 1.1371)
  point P46 (-54.0094, 1.8871)
  point P68 (-59.3084, -0.8629)
  point P60 (-58.0094, -0.1129)
  point P82 (-39.3084, 9.1371)
  point P74 (-38.0094, 9.8871)
  coincident P2 L1
  coincident P2 L4
  tangent L1 A1
  tangent L4 A1
  coincident P3 L3
  coincident P3 L4
  tangent L3 A2
  tangent L4 A2
  equal A1 A2
  tangent L2 A3
  tangent L3 A3
  equal A1 A3
  tangent L1 A4
  tangent L2 A4
  coincident P25 L5
  coincident P25 L6
  tangent L5 A6
  tangent L6 A6
  coincident P18 L7
  coincident P18 L6
  tangent A5 L7
  tangent A5 L6
  equal A5 A6
  tangent A8 L8
  tangent L7 A8
  equal A6 A8
  tangent L5 A7
  tangent A7 L8
  coincident P40 L11
  coincident P40 L12
  tangent A10 L11
  tangent A10 L12
  coincident P32 L9
  coincident P32 L12
  tangent L9 A12
  tangent L12 A12
  equal A10 A12
  tangent A9 L10
  tangent A9 L9
  equal A9 A10
  tangent L11 A11
  tangent L10 A11
  coincident P54 L15
  coincident P54 L16
  tangent A14 L15
  tangent A14 L16
  coincident P46 L13
  coincident P46 L16
  tangent L13 A16
  tangent L16 A16
  equal A14 A16
  tangent A13 L14
  tangent A13 L13
  equal A13 A14
  tangent L15 A15
  tangent L14 A15
  coincident P68 L19
  coincident P68 L20
  tangent A18 L19
  tangent A18 L20
  coincident P60 L17
  coincident P60 L20
  tangent L17 A20
  tangent L20 A20
  equal A18 A20
  tangent A17 L18
  tangent A17 L17
  equal A17 A18
  tangent L19 A19
  tangent L18 A19
  coincident P82 L23
  coincident P82 L24
  tangent A22 L23
  tangent A22 L24
  coincident P74 L21
  coincident P74 L24
  tangent L21 A24
  tangent L24 A24
  equal A22 A24
  tangent A21 L22
  tangent A21 L21
  equal A21 A22
  tangent L23 A23
  tangent L22 A23
  dimension "d145" distance P2 P3 = 1.5
  dimension "d146" radius A1 = 0.5
  dimension "d156" radius A4 = 0.5
  dimension "d175" distance P18 P25 = 1.5
  dimension "d176" radius A6 = 0.5
  dimension "d177" radius A7 = 0.5
  dimension "d178" distance P32 P40 = 1.5
  dimension "d179" radius A10 = 0.5
  dimension "d180" radius A11 = 0.5
  dimension "d181" distance P46 P54 = 1.5
  dimension "d182" radius A14 = 0.5
  dimension "d183" radius A15 = 0.5
  dimension "d184" distance P60 P68 = 1.5
  dimension "d185" radius A18 = 0.5
  dimension "d186" radius A19 = 0.5
  dimension "d187" distance P74 P82 = 1.5
  dimension "d188" radius A22 = 0.5
  dimension "d189" radius A23 = 0.5
extrude "Extrude15" cut sketch "Sketch23" against normal blind 3
extrude "Extrude16" add sketch "Sketch22" profile of L1 L2 L3 L4 A1 A2 A3 A4 A5 A6 A7 L5 A8 L6 L7 L8 along normal blind 0.5
fillet "Fillet5" radius 0.5
fillet "Fillet6" radius 0.5
fillet "Fillet7" radius 0.15
fillet "Fillet8" radius 0.7
fillet "Fillet9" radius 0.7
sketch "Sketch24" plane through (0, 0, 16) normal (0, 0, 1) x axis (-1, 0, 0)
sketch "Sketch25" plane through (0, 0, 16) normal (0, 0, 1) x axis (-1, 0, 0)
  line L1 (-38.47, 22) -> (-25.47, 22)
  line L2 (-39.47, 19) -> (-39.47, 21)
  line L3 (-25.47, 18) -> (-38.47, 18)
  line L4 (-24.47, 21) -> (-24.47, 19)
  line L5 (5.53, 23.27) -> (5.53, -81.33)
  curve K1 (-37.3422, 18.9501) -> (-37.439, 18.8303)
  curve K2 (-37.2294, 19.1163) -> (-37.3422, 18.9501)
  curve K3 (-37.1264, 19.2175) -> (-37.2294, 19.1163)
  curve K4 (-37.0001, 19.2226) -> (-37.1264, 19.2175)
  curve K5 (-36.8722, 19.1852) -> (-37.0001, 19.2226)
  curve K6 (-36.7764, 19.1647) -> (-36.8722, 19.1852)
  curve K7 (-36.4902, 19.1654) -> (-36.7764, 19.1647)
  curve K8 (-36.3848, 19.1705) -> (-36.4902, 19.1654)
  curve K9 (-36.3298, 19.1394) -> (-36.3848, 19.1705)
  curve K10 (-36.1124, 18.8542) -> (-36.3298, 19.1394)
  curve K11 (-36.0763, 18.8096) -> (-36.1124, 18.8542)
  curve K12 (-36.0169, 18.8702) -> (-36.0763, 18.8096)
  curve K13 (-35.8877, 19.0744) -> (-36.0169, 18.8702)
  curve K14 (-35.8587, 19.1153) -> (-35.8877, 19.0744)
  curve K15 (-35.7326, 19.2882) -> (-35.8587, 19.1153)
  curve K16 (-35.6753, 19.3337) -> (-35.7326, 19.2882)
  curve K17 (-35.6001, 19.3437) -> (-35.6753, 19.3337)
  curve K18 (-35.5769, 19.2627) -> (-35.6001, 19.3437)
  curve K19 (-35.6771, 19.0995) -> (-35.5769, 19.2627)
  curve K20 (-35.815, 18.908) -> (-35.6771, 19.0995)
  curve K21 (-35.9339, 18.6824) -> (-35.815, 18.908)
  curve K22 (-35.9612, 18.6022) -> (-35.9339, 18.6824)
  curve K23 (-36.0973, 18.5664) -> (-35.9612, 18.6022)
  curve K24 (-36.1161, 18.5882) -> (-36.0973, 18.5664)
  curve K25 (-36.2433, 18.8099) -> (-36.1161, 18.5882)
  curve K26 (-36.2966, 18.8842) -> (-36.2433, 18.8099)
  curve K27 (-36.3681, 18.9565) -> (-36.2966, 18.8842)
  curve K28 (-36.4589, 18.9942) -> (-36.3681, 18.9565)
  curve K29 (-36.846, 19.016) -> (-36.4589, 18.9942)
  curve K30 (-36.9414, 19.0385) -> (-36.846, 19.016)
  curve K31 (-37.102, 18.986) -> (-36.9414, 19.0385)
  curve K32 (-37.3404, 18.6796) -> (-37.102, 18.986)
  curve K33 (-37.3954, 18.5959) -> (-37.3404, 18.6796)
  curve K34 (-37.5309, 18.5861) -> (-37.3954, 18.5959)
  curve K35 (-37.5748, 18.6731) -> (-37.5309, 18.5861)
  curve K36 (-37.683, 19.0368) -> (-37.5748, 18.6731)
  curve K37 (-37.7398, 19.1887) -> (-37.683, 19.0368)
  curve K38 (-37.7508, 19.2432) -> (-37.7398, 19.1887)
  curve K39 (-37.6718, 19.2952) -> (-37.7508, 19.2432)
  curve K40 (-37.5894, 19.23) -> (-37.6718, 19.2952)
  curve K41 (-37.4954, 18.9357) -> (-37.5894, 19.23)
  curve K42 (-37.4588, 18.8331) -> (-37.4954, 18.9357)
  curve K43 (-37.439, 18.8303) -> (-37.4588, 18.8331)
  curve K44 (-36.8145, 21.2212) -> (-36.9502, 21.2117)
  curve K45 (-36.7768, 21.2193) -> (-36.8145, 21.2212)
  curve K46 (-36.4468, 21.1406) -> (-36.7768, 21.2193)
  curve K47 (-36.2922, 21.1074) -> (-36.4468, 21.1406)
  curve K48 (-36.0061, 20.9949) -> (-36.2922, 21.1074)
  curve K49 (-35.9125, 20.9355) -> (-36.0061, 20.9949)
  curve K50 (-35.7484, 20.7999) -> (-35.9125, 20.9355)
  curve K51 (-35.6992, 20.7298) -> (-35.7484, 20.7999)
  curve K52 (-35.714, 20.639) -> (-35.6992, 20.7298)
  curve K53 (-35.812, 20.6523) -> (-35.714, 20.639)
  curve K54 (-35.8452, 20.6811) -> (-35.812, 20.6523)
  curve K55 (-36.1453, 20.8767) -> (-35.8452, 20.6811)
  curve K56 (-36.4633, 20.9719) -> (-36.1453, 20.8767)
  curve K57 (-36.8966, 21.0382) -> (-36.4633, 20.9719)
  curve K58 (-37.0756, 21.0164) -> (-36.8966, 21.0382)
  curve K59 (-37.4674, 20.883) -> (-37.0756, 21.0164)
  curve K60 (-37.5607, 20.8231) -> (-37.4674, 20.883)
  curve K61 (-37.6927, 20.8307) -> (-37.5607, 20.8231)
  curve K62 (-37.7129, 20.9686) -> (-37.6927, 20.8307)
  curve K63 (-37.5795, 21.0432) -> (-37.7129, 20.9686)
  curve K64 (-37.5219, 21.058) -> (-37.5795, 21.0432)
  curve K65 (-37.3418, 21.1439) -> (-37.5219, 21.058)
  curve K66 (-36.9502, 21.2117) -> (-37.3418, 21.1439)
  curve K67 (-36.6698, 20.627) -> (-36.7701, 20.5917)
  curve K68 (-36.5322, 20.6135) -> (-36.6698, 20.627)
  curve K69 (-36.4983, 20.5267) -> (-36.5322, 20.6135)
  curve K70 (-36.564, 20.4884) -> (-36.4983, 20.5267)
  curve K71 (-36.6429, 20.4677) -> (-36.564, 20.4884)
  curve K72 (-36.6543, 20.3289) -> (-36.6429, 20.4677)
  curve K73 (-36.5912, 20.2603) -> (-36.6543, 20.3289)
  curve K74 (-36.6099, 20.1532) -> (-36.5912, 20.2603)
  curve K75 (-36.8305, 20.1321) -> (-36.6099, 20.1532)
  curve K76 (-36.8702, 20.274) -> (-36.8305, 20.1321)
  curve K77 (-36.8516, 20.4643) -> (-36.8702, 20.274)
  curve K78 (-36.9553, 20.5139) -> (-36.8516, 20.4643)
  curve K79 (-37.0635, 20.5543) -> (-36.9553, 20.5139)
  curve K80 (-37.0168, 20.6695) -> (-37.0635, 20.5543)
  curve K81 (-36.8244, 20.6451) -> (-37.0168, 20.6695)
  curve K82 (-36.7701, 20.5917) -> (-36.8244, 20.6451)
  curve K83 (-35.5708, 19.9353) -> (-35.7862, 19.9775)
  curve K84 (-35.1245, 19.8487) -> (-35.5708, 19.9353)
  curve K85 (-35.0387, 19.7547) -> (-35.1245, 19.8487)
  curve K86 (-35.0994, 19.6949) -> (-35.0387, 19.7547)
  curve K87 (-35.1888, 19.7099) -> (-35.0994, 19.6949)
  curve K88 (-35.7275, 19.8028) -> (-35.1888, 19.7099)
  curve K89 (-35.8665, 19.8871) -> (-35.7275, 19.8028)
  curve K90 (-35.8097, 19.9755) -> (-35.8665, 19.8871)
  curve K91 (-35.7869, 19.9741) -> (-35.8097, 19.9755)
  curve K92 (-35.7862, 19.9775) -> (-35.7869, 19.9741)
  curve K93 (-37.9325, 20.0467) -> (-37.9928, 20.0479)
  curve K94 (-37.8823, 20.0126) -> (-37.9325, 20.0467)
  curve K95 (-37.9092, 19.9627) -> (-37.8823, 20.0126)
  curve K96 (-38.0058, 19.9237) -> (-37.9092, 19.9627)
  curve K97 (-38.4283, 19.8425) -> (-38.0058, 19.9237)
  curve K98 (-38.6353, 19.7982) -> (-38.4283, 19.8425)
  curve K99 (-38.7237, 19.8232) -> (-38.6353, 19.7982)
  curve K100 (-38.7295, 19.8949) -> (-38.7237, 19.8232)
  curve K101 (-38.6924, 19.926) -> (-38.7295, 19.8949)
  curve K102 (-38.6053, 19.9497) -> (-38.6924, 19.926)
  curve K103 (-38.1875, 20.0219) -> (-38.6053, 19.9497)
  curve K104 (-37.9938, 20.0519) -> (-38.1875, 20.0219)
  curve K105 (-37.9928, 20.0479) -> (-37.9938, 20.0519)
  curve K106 (-38.434, 20.2466) -> (-37.9917, 20.1895)
  curve K107 (-38.5345, 20.2772) -> (-38.434, 20.2466)
  curve K108 (-38.5858, 20.4041) -> (-38.5345, 20.2772)
  curve K109 (-38.5013, 20.4302) -> (-38.5858, 20.4041)
  curve K110 (-38.1305, 20.365) -> (-38.5013, 20.4302)
  curve K111 (-37.9722, 20.3208) -> (-38.1305, 20.365)
  curve K112 (-37.9462, 20.3067) -> (-37.9722, 20.3208)
  curve K113 (-37.912, 20.2352) -> (-37.9462, 20.3067)
  curve K114 (-37.9917, 20.1895) -> (-37.912, 20.2352)
  curve K115 (-35.8712, 20.1632) -> (-35.7976, 20.1286)
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  point P3 (-39.47, 22)
  point P2 (-24.47, 22)
  point P4 (-24.47, 18)
  horizontal L1
  vertical L2
  horizontal L3
  vertical L4
  coincident P3 L1
  coincident P3 L2
  coincident P2 L1
  coincident P2 L4
  coincident P4 L3
  coincident P4 L4
  dimension "d204" distance P2 P3 = 15
  dimension "d205" distance P2 P4 = 4
  dimension "d206" distance L4 L5 = 30
  dimension "d207" radius = 1
extrude "Extrude17" cut sketch "Sketch25" against normal blind 0.25
sketch "Sketch26" plane through (0, 0, 0) normal (0, 0, -1) x axis (1, 0, 0)
  line L1 (-3.53, 24.57) -> (54.47, 24.57)
  line L2 (-4.83, -82.73) -> (-4.83, 23.27)
  line L3 (67.47, -84.03) -> (-3.53, -84.03)
  line L4 (68.77, 10.27) -> (68.77, -82.73)
  line L5 (59, -79) -> (64, -79)
  line L6 (59, 0) -> (59, -79)
  line L7 (64, 0) -> (59, 0)
  line L8 (64, -79) -> (64, 0)
  line L9 (5, -79) -> (0, -79)
  line L10 (5, 0) -> (5, -79)
  line L11 (0, 0) -> (5, 0)
  line L12 (0, -79) -> (0, 0)
  arc A1 centre (54.47, 10.27) radius 14.3 clockwise from (54.47, 24.57) to (68.77, 10.27)
  arc A2 centre (-3.53, 23.27) radius 1.3 clockwise from (-4.83, 23.27) to (-3.53, 24.57)
  arc A3 centre (-3.53, -82.73) radius 1.3 clockwise from (-3.53, -84.03) to (-4.83, -82.73)
  arc A4 centre (67.47, -82.73) radius 1.3 clockwise from (68.77, -82.73) to (67.47, -84.03)
  point P14 (64, -79)
  point P15 (59, -79)
  horizontal L5
  vertical L6
  horizontal L7
  vertical L8
  horizontal L9
  vertical L10
  horizontal L11
  vertical L12
  dimension "d237" distance P14 P15 = 5
sketch "Sketch27" plane through (-5.53, 0, 0) normal (-1, 0, 0) x axis (0, -1, 0)
sketch "Sketch28" plane through (0, -25.27, 0) normal (0, -1, 0) x axis (1, 0, 0)
  line L1 (54.47, 0.7) -> (-3.53, 0.7)
  line L2 (54.47, 13) -> (54.47, 0.7)
  line L3 (-3.53, 13) -> (54.47, 13)
  line L4 (-3.53, 0.7) -> (-3.53, 13)
  line L5 (54.47, 8.5) -> (-3.5, 8.5)
  line L6 (54.47, 7.7) -> (-3.53, 7.7)
  line L7 (-3.53, 8.5) -> (-3.5, 8.5)
  line L8 (-3.53, 8.5) -> (-3.53, 7.7)
  line L9 (54.47, 8.5) -> (54.47, 7.7)
  point P7 (54.47, 8.5)
  point P8 (-3.53, 7.7)
  point P9 (54.47, 7.7)
  point P10 (-3.53, 8.5)
  coincident L2 P7
  perpendicular L2 L5
  coincident L4 P8
  coincident L2 P9
  perpendicular L2 L6
  coincident L4 P10
  perpendicular L4 L7
  dimension "d214" distance L5 L6 = 0.8
sketch "Sketch29" plane through (0, 0, 0) normal (0, 1, 0) x axis (1, 0, 0)
extrude "Extrude18" cut sketch "Sketch28" profile of L2 L4 L5 L6 L7 L8 L9 against normal blind 0.25
extrude "Extrude19" cut sketch "Sketch19" profile of L3 L5 L6 L7 L8 L9 L10 L11 L12 against normal blind 0.25
move "Move2"
sketch "Sketch9" plane through (0, 0, 0) normal (0, 1, 0) x axis (1, 0, 0)
surface_patch "SurfacePatch1"
extrude "Extrude5" add of existing geometry blind -7
surface_patch "SurfacePatch2"
extrude "Extrude6" add of existing geometry blind -7
extrude "Extrude21" add of existing geometry blind 0.25
extrude "Extrude22" add of existing geometry blind 0.25
move "Move5"
surface_patch "SurfacePatch3"
extrude "Extrude7" add of existing geometry blind -7
surface_patch "SurfacePatch4"
extrude "Extrude8" add of existing geometry blind -7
